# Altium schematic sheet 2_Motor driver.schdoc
size 431 x 309 mm
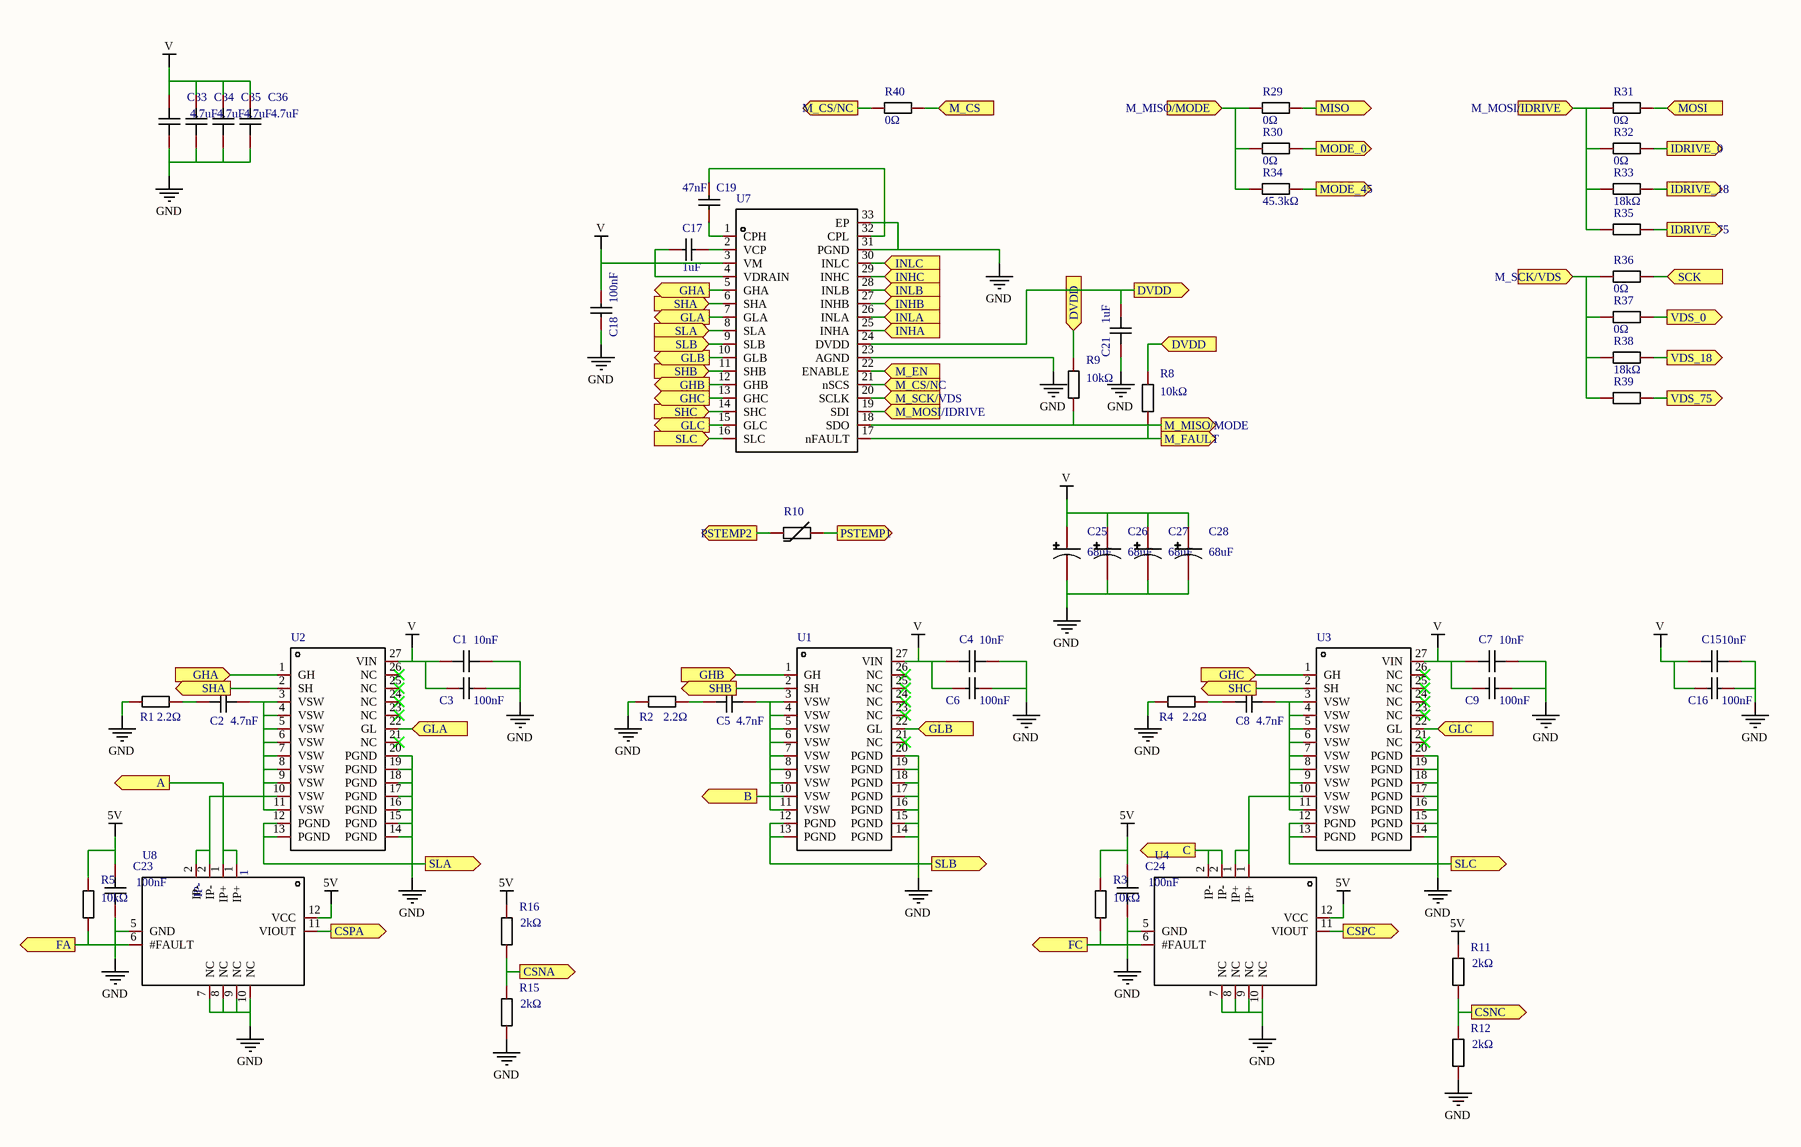
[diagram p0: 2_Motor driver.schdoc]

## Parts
C1  value 10nF  [C0402]  (hidden comment: CC0402KRX7R0BB103)
C2  value 4.7nF  [C0402]  (hidden comment: GRM155R72A472KA01D)
C3  value 100nF  [C0805]  (hidden comment: CL21B104KCFNNNE)
C4  value 10nF  [C0402]  (hidden comment: CC0402KRX7R0BB103)
C5  value 4.7nF  [C0402]  (hidden comment: GRM155R72A472KA01D)
C6  value 100nF  [C0805]  (hidden comment: CL21B104KCFNNNE)
C7  value 10nF  [C0402]  (hidden comment: CC0402KRX7R0BB103)
C8  value 4.7nF  [C0402]  (hidden comment: GRM155R72A472KA01D)
C9  value 100nF  [C0805]  (hidden comment: CL21B104KCFNNNE)
C15  value 10nF  [C0402]  (hidden comment: CC0402KRX7R0BB103)
C16  value 100nF  [C0805]  (hidden comment: CL21B104KCFNNNE)
C17  value 1uF  [C0805]  (hidden comment: C0805X105K101T)
C18  value 100nF  [C0805]  (hidden comment: CL21B104KCFNNNE)
C19  value 47nF  [C0805]  (hidden comment: C2012X7R2A473KT0L0U)
C21  value 1uF  [C0402]  (hidden comment: CL05A105KA5NQNC)
C23  value 100nF  [C0402]  (hidden comment: CC0402KRX7R7BB104)
C24  value 100nF  [C0402]  (hidden comment: CC0402KRX7R7BB104)
C25  value 68uF  [CAP-SMD_BD6.3-L6.6-W6.6-LS7.6-FD]  (hidden comment: VKMC1201J680MV)
C26  value 68uF  [CAP-SMD_BD6.3-L6.6-W6.6-LS7.6-FD]  (hidden comment: VKMC1201J680MV)
C27  value 68uF  [CAP-SMD_BD6.3-L6.6-W6.6-LS7.6-FD]  (hidden comment: VKMC1201J680MV)
C28  value 68uF  [CAP-SMD_BD6.3-L6.6-W6.6-LS7.6-FD]  (hidden comment: VKMC1201J680MV)
C33  value 4.7uF  [C1206]  (hidden comment: GRM31CC72A475KE11L)
C34  value 4.7uF  [C1206]  (hidden comment: GRM31CC72A475KE11L)
C35  value 4.7uF  [C1206]  (hidden comment: GRM31CC72A475KE11L)
C36  value 4.7uF  [C1206]  (hidden comment: GRM31CC72A475KE11L)
R1  value 2.2Ω  [R0805]  (hidden comment: 0805W8F220KT5E)
R2  value 2.2Ω  [R0805]  (hidden comment: 0805W8F220KT5E)
R3  value 10kΩ  [R0402]  (hidden comment: 0402WGF1002TCE)
R4  value 2.2Ω  [R0805]  (hidden comment: 0805W8F220KT5E)
R5  value 10kΩ  [R0402]  (hidden comment: 0402WGF1002TCE)
R8  value 10kΩ  [R0402]  (hidden comment: 0402WGF1002TCE)
R9  value 10kΩ  [R0402]  (hidden comment: 0402WGF1002TCE)
R10  NCP15XH103F03RC  [R0402]  (value not drawn)
R11  value 2kΩ  [R0402]  (hidden comment: AR02BTC2001)
R12  value 2kΩ  [R0402]  (hidden comment: AR02BTC2001)
R15  value 2kΩ  [R0402]  (hidden comment: AR02BTC2001)
R16  value 2kΩ  [R0402]  (hidden comment: AR02BTC2001)
R29  value 0Ω  [R0402]  (hidden comment: RC0402FR-070RL)
R30  value 0Ω  [R0402]  (hidden comment: RC0402FR-070RL)
R31  value 0Ω  [R0402]  (hidden comment: RC0402FR-070RL)
R32  value 0Ω  [R0402]  (hidden comment: RC0402FR-070RL)
R33  value 18kΩ  [R0402]  (hidden comment: RC0402FR-0718KL)
R34  value 45.3kΩ  [R0402]  (hidden comment: 0402WGF4532TCE)
R35  0402WGF7502TCE  [R0402]  (value not drawn)
R36  value 0Ω  [R0402]  (hidden comment: RC0402FR-070RL)
R37  value 0Ω  [R0402]  (hidden comment: RC0402FR-070RL)
R38  value 18kΩ  [R0402]  (hidden comment: RC0402FR-0718KL)
R39  0402WGF7502TCE  [R0402]  (value not drawn)
R40  value 0Ω  [R0402]  (hidden comment: RC0402FR-070RL)
U1  CSD88599Q5DCT  (value not drawn)
U2  CSD88599Q5DCT  (value not drawn)
U3  CSD88599Q5DCT  (value not drawn)
U4  ACS711KEXLT-31AB-T  [IC-SMD_ACS711KEXLT-15AB-T]  (value not drawn)
U7  DRV8320SRTVR  [WQFN-32_L5.0-W5.0-P0.50-TL-EP3.5]  (value not drawn)
U8  NAME: IP-  NUMBER: 1  [IC-SMD_ACS711KEXLT-15AB-T]  (hidden comment: ACS711KEXLT-31AB-T)

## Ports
A (out), B (out), C (out), CSNA (out), CSNC (out), CSPA (out), CSPC (out), DVDD (in), DVDD (out), FA (out), FC (out), GHA (in), GHA (out), GHB (in), GHB (out), GHC (in), GHC (out), GLA (in), GLA (out), GLB (in), GLB (out), GLC (in), GLC (out), IDRIVE_0 (out), IDRIVE_18 (out), IDRIVE_75 (out), INHA (in), INHB (in), INHC (in), INLA (in), INLB (in), INLC (in), M_CS (in), M_CS/NC (in), M_CS/NC (out), M_EN (in), M_FAULT (out), M_MISO/MODE (in), M_MISO/MODE (out), M_MOSI/IDRIVE (in), M_SCK/VDS (in), MISO (out), MODE_0 (out), MODE_45 (out), MOSI (in), PSTEMP1 (out), PSTEMP2 (out), SCK (in), SHA (in), SHA (out), SHB (in), SHB (out), SHC (in), SHC (out), SLA (in), SLA (out), SLB (in), SLB (out), SLC (in), SLC (out), VDS_0 (out), VDS_18 (out), VDS_75 (out)

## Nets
5V: C23.2 C24.2 R3.2 R5.2 R11.2 R16.2 U4.12(VCC) U8.12(VCC)
GND: C1.2 C3.2 C4.2 C6.2 C7.2 C9.2 C15.2 C16.2 C18.1 C21.1 C23.1 C24.1 C25.2 C26.2 C27.2 C28.2 C33.2 C34.2 C35.2 C36.2 R1.1 R2.1 R4.1 R12.1 R15.1 U1.12(PGND) U1.13(PGND) U1.14(PGND) U1.15(PGND) U1.16(PGND) U1.17(PGND) U1.18(PGND) U1.19(PGND) U1.20(PGND) U2.12(PGND) U2.13(PGND) U2.14(PGND) U2.15(PGND) U2.16(PGND) U2.17(PGND) U2.18(PGND) U2.19(PGND) U2.20(PGND) U3.12(PGND) U3.13(PGND) U3.14(PGND) U3.15(PGND) U3.16(PGND) U3.17(PGND) U3.18(PGND) U3.19(PGND) U3.20(PGND) U4.5(GND) U4.7(NC) U4.8(NC) U4.9(NC) U4.10(NC) U7.8(SLA) U7.9(SLB) U7.16(SLC) U7.23(AGND) U7.31(PGND) U7.33(EP) U8.5(GND) U8.7(NC) U8.8(NC) U8.9(NC) U8.10(NC) ; port SLA, port SLB, port SLC
V: C1.1 C3.1 C4.1 C6.1 C7.1 C9.1 C15.1 C16.1 C17.1 C18.2 C25.1 C26.1 C27.1 C28.1 C33.1 C34.1 C35.1 C36.1 U1.27(VIN) U2.27(VIN) U3.27(VIN) U7.3(VM) U7.4(VDRAIN)
A: U8.1(IP+) ; port A
B: C5.2 U1.3(VSW) U1.4(VSW) U1.5(VSW) U1.6(VSW) U1.7(VSW) U1.8(VSW) U1.9(VSW) U1.10(VSW) U1.11(VSW) ; port B
C: U4.2(IP-) ; port C
CSNA: R15.2 R16.1 ; port CSNA
CSNC: R11.1 R12.2 ; port CSNC
CSPA: U8.11(VIOUT) ; port CSPA
CSPC: U4.11(VIOUT) ; port CSPC
DVDD: C21.2 R8.2 R9.2 U7.24(DVDD) ; port DVDD
FA: R5.1 U8.6(#FAULT) ; port FA
FC: R3.1 U4.6(#FAULT) ; port FC
GHA: U2.1(GH) U7.5(GHA) ; port GHA
GHB: U1.1(GH) U7.12(GHB) ; port GHB
GHC: U3.1(GH) U7.13(GHC) ; port GHC
GLA: U2.22(GL) U7.7(GLA) ; port GLA
GLB: U1.22(GL) U7.10(GLB) ; port GLB
GLC: U3.22(GL) U7.15(GLC) ; port GLC
IDRIVE_0: R32.2 ; port IDRIVE_0
IDRIVE_18: R33.2 ; port IDRIVE_18
IDRIVE_75: R35.2 ; port IDRIVE_75
INHA: U7.25(INHA) ; port INHA
INHB: U7.27(INHB) ; port INHB
INHC: U7.29(INHC) ; port INHC
INLA: U7.26(INLA) ; port INLA
INLB: U7.28(INLB) ; port INLB
INLC: U7.30(INLC) ; port INLC
M_CS: R40.2 ; port M_CS
M_CS/NC: R40.1 U7.21(nSCS) ; port M_CS/NC
M_EN: U7.22(ENABLE) ; port M_EN
M_FAULT: R8.1 R9.1 R29.1 R30.1 R34.1 U7.17(nFAULT) U7.18(SDO) ; port M_MISO/MODE, port M_FAULT
M_MOSI/IDRIVE: R31.1 R32.1 R33.1 R35.1 U7.19(SDI) ; port M_MOSI/IDRIVE
M_SCK/VDS: R36.1 R37.1 R38.1 R39.1 U7.20(SCLK) ; port M_SCK/VDS
MISO: R29.2 ; port MISO
MODE_0: R30.2 ; port MODE_0
MODE_45: R34.2 ; port MODE_45
MOSI: R31.2 ; port MOSI
PSTEMP1: R10.2 ; port PSTEMP1
PSTEMP2: R10.1 ; port PSTEMP2
SCK: R36.2 ; port SCK
SHA: U2.2(SH) U7.6(SHA) ; port SHA
SHB: U1.2(SH) U7.11(SHB) ; port SHB
SHC: U3.2(SH) U7.14(SHC) ; port SHC
VDS_0: R37.2 ; port VDS_0
VDS_18: R38.2 ; port VDS_18
VDS_75: R39.2 ; port VDS_75
NetC2_1: C2.1 R1.2
NetC2_2: C2.2 U2.3(VSW) U2.4(VSW) U2.5(VSW) U2.6(VSW) U2.7(VSW) U2.8(VSW) U2.9(VSW) U2.10(VSW) U2.11(VSW) U8.2(IP-)
NetC5_1: C5.1 R2.2
NetC8_1: C8.1 R4.2
NetC8_2: C8.2 U3.3(VSW) U3.4(VSW) U3.5(VSW) U3.6(VSW) U3.7(VSW) U3.8(VSW) U3.9(VSW) U3.10(VSW) U3.11(VSW) U4.1(IP+)
NetC17_2: C17.2 U7.2(VCP)
NetC19_1: C19.1 U7.32(CPL)
NetC19_2: C19.2 U7.1(CPH)

Not connected (* = marked no-connect by the designer): U1 21(NC)* 23(NC)* 24(NC)* 25(NC)* 26(NC)*; U2 21(NC)* 23(NC)* 24(NC)* 25(NC)* 26(NC)*; U3 21(NC)* 23(NC)* 24(NC)* 25(NC)* 26(NC)*

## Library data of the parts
C1 C4 C7 C15 = CC0402KRX7R0BB103: Capacitance:10nF Tolerance:±10% Tolerance:±10% Voltage Rated:100V Temperature Coefficient:X7R; Manufacturer: YAGEO(国巨); Add into BOM: yes; Tolerance: ±10%; Voltage Rated: 100V; Temperature Coefficient: X7R
C2 C5 C8 = GRM155R72A472KA01D: Capacitance:4.7nF Tolerance:±10% Tolerance:±10% Voltage Rated:100V Temperature Coefficient:X7R; Manufacturer: muRata(村田); Add into BOM: yes; Tolerance: ±10%; Voltage Rated: 100V; Temperature Coefficient: X7R
C3 C6 C9 C16 C18 = CL21B104KCFNNNE: Capacitance:100nF Tolerance:±10% Tolerance:±10% Voltage Rated:100V Temperature Coefficient:X7R; Manufacturer: SAMSUNG(三星); Add into BOM: yes; Tolerance: ±10%; Voltage Rated: 100V; Temperature Coefficient: X7R
C17 = C0805X105K101T: Capacitance:1uF Tolerance:±10% Tolerance:±10% Voltage Rated:100V Temperature Coefficient:X7R; Manufacturer: IHHEC(禾伸堂); Add into BOM: yes; Tolerance: ±10%; Voltage Rated: 100V; Temperature Coefficient: X7R
C19 = C2012X7R2A473KT0L0U: Capacitance:47nF Tolerance:±10% Tolerance:±10% Voltage Rated:100V Temperature Coefficient:X7R; Manufacturer: TDK; Add into BOM: yes; Tolerance: ±10%; Voltage Rated: 100V; Temperature Coefficient: X7R
C21 = CL05A105KA5NQNC: Capacitance:1uF Tolerance:±10% Tolerance:±10% Voltage Rated:25V Temperature Coefficient:X5R; Manufacturer: SAMSUNG(三星); Add into BOM: yes; Tolerance: ±10%; Voltage Rated: 25V; Temperature Coefficient: X5R
C23 C24 = CC0402KRX7R7BB104: Capacitance:100nF Tolerance:±10% Tolerance:±10% Voltage Rated:16V Temperature Coefficient:X7R; Manufacturer: YAGEO(国巨); Add into BOM: yes; Tolerance: ±10%; Voltage Rated: 16V; Temperature Coefficient: X7R
C25-C28 = VKMC1201J680MV: Capacitance:68uF Tolerance:±20% Tolerance:±20% Rated Voltage:63V φD:6.3mm L:12mm Ripple Current:724mA@100kHz Equivalent Series Resistance(ESR):- Lifetime @ Temp:9000hrs@105 Operating Temperature:-55~+105 Operating Temperature:-55~+105; Manufacturer: Ymin(永铭); Add into BOM: yes; Tolerance: ±20%; Rated Voltage: 63V; φD: 6.3mm; L: 12mm
C33-C36 = GRM31CC72A475KE11L: Capacitance:4.7uF Tolerance:±10% Tolerance:±10% Voltage Rated:100V Temperature Coefficient:X7S; Manufacturer: muRata(村田); Add into BOM: yes; Tolerance: ±10%; Voltage Rated: 100V; Temperature Coefficient: X7S
R1 R2 R4 = 0805W8F220KT5E: Type:厚膜电阻 Resistance:2.2Ω Tolerance:±1% Power(Watts):125mW Temperature Coefficient:±400ppm/ Temperature Coefficient:±400ppm/ Overload Voltage (Max):150V Operating Temperature Range:-55~+155 Operating Temperature Range:-55~+155; Manufacturer: UNI-ROYAL(厚声); Add into BOM: yes; Tolerance: ±1%; Power(Watts): 125mW; Overload Voltage (Max): 150V
R3 R5 R8 R9 = 0402WGF1002TCE: Type:厚膜电阻 Resistance:10kΩ Tolerance:±1% Tolerance:±1% Power(Watts):1/16W Temperature Coefficient:±100ppm/ Temperature Coefficient:±100ppm/ Overload Voltage (Max):50V Operating Temperature Range:-55~+155 Operating Temperature Range:-55~+155; Manufacturer: UNI-ROYAL(厚声); Add into BOM: yes; Tolerance: ±1%; Power(Watts): 1/16W; Overload Voltage (Max): 50V
R10 = NCP15XH103F03RC: Resistance @ 25:10kΩ Resistance Tolerance:±1% B Constant Tolerance:±1% B Constant (25/50):3380K Power:100mW Steady State Current (Max):0.31mA B Constant (25/75):- B Constant (25/85):3334K B Constant (25/100):3455K Operating Temperature:-40~+125; Manufacturer: muRata(村田); Add into BOM: yes; Resistance @ 25℃: 10kΩ; Resistance Tolerance: ±1%; B Constant (25℃/50℃): 3380K; Power: 100mW; Steady State Current (Max): 0.31mA; B Constant (25℃/85℃): 3334K; B Constant (25℃/100℃): 3455K
R11 R12 R15 R16 = AR02BTC2001: Type:薄膜电阻 Resistance:2kΩ Tolerance:±0.1% Power(Watts):1/16W Temperature Coefficient:±25ppm/ Temperature Coefficient:±25ppm/ Overload Voltage (Max):25V Operating Temperature Range:-55~+155 Operating Temperature Range:-55~+155; Manufacturer: 光颉(Viking); Add into BOM: yes; Tolerance: ±0.1%; Power(Watts): 1/16W; Temperature Coefficient: ±25ppm/; Overload Voltage (Max): 25V
R29 R31 R36 R40 = RC0402FR-070RL: Temperature Coefficient:- Temperature Coefficient:- Power(Watts):1/16W Tolerance:±1% Resistance:0Ω Overload Voltage (Max):50V Operating Temperature Range:-55~+155 Operating Temperature Range:-55~+155; Manufacturer: YAGEO(国巨); Add into BOM: no; Convert to PCB: yes; Power(Watts): 1/16W; Tolerance: ±1%; Overload Voltage (Max): 50V
R30 R32 R37 = RC0402FR-070RL: Temperature Coefficient:- Temperature Coefficient:- Power(Watts):1/16W Tolerance:±1% Resistance:0Ω Overload Voltage (Max):50V Operating Temperature Range:-55~+155 Operating Temperature Range:-55~+155; Manufacturer: YAGEO(国巨); Add into BOM: yes; Power(Watts): 1/16W; Tolerance: ±1%; Overload Voltage (Max): 50V
R33 R38 = RC0402FR-0718KL: Type:厚膜电阻 Resistance:18kΩ Tolerance:±1% Tolerance:±1% Power(Watts):62.5mW Temperature Coefficient:±100ppm/ Temperature Coefficient:±100ppm/ Overload Voltage (Max):50V Operating Temperature Range:-55~+155 Operating Temperature Range:-55~+155; Manufacturer: YAGEO(国巨); Add into BOM: yes; Tolerance: ±1%; Power(Watts): 62.5mW; Overload Voltage (Max): 50V
R34 = 0402WGF4532TCE: Type:厚膜电阻 Resistance:45.3kΩ Tolerance:±1% Tolerance:±1% Power(Watts):1/16W Temperature Coefficient:±100ppm/ Temperature Coefficient:±100ppm/ Overload Voltage (Max):50V Operating Temperature Range:-55~+155 Operating Temperature Range:-55~+155; Manufacturer: UNI-ROYAL(厚声); Add into BOM: yes; Tolerance: ±1%; Power(Watts): 1/16W; Overload Voltage (Max): 50V
R35 R39 = 0402WGF7502TCE: Manufacturer: UNI-ROYAL(厚声); Add into BOM: yes
U1-U3 = CSD88599Q5DCT: Manufacturer: TI(德州仪器); Add into BOM: yes
U4 U8 = ACS711KEXLT-31AB-T: Manufacturer: ALLEGRO(美国埃戈罗); Add into BOM: yes
U7 = DRV8320SRTVR: Manufacturer: TI(德州仪器); Add into BOM: yes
